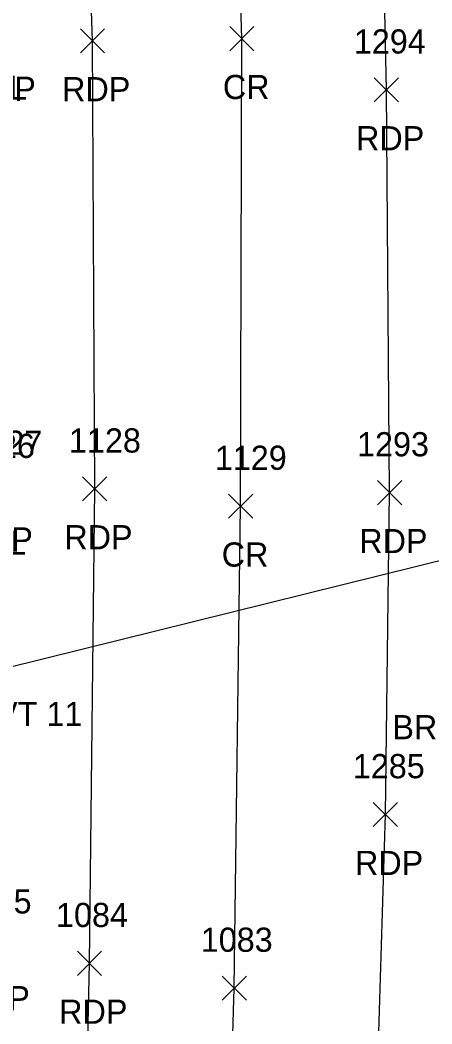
# Model space of a CAD drawing. Extents: x 1618262 to 1622220, y 273782 to 283685.
# Drawn here: x 1622046.2 to 1622080.2, y 282665.6 to 282748.6 of the extents above; entities that cross this region are included whole.
import ezdxf

# ---------------------------------------------------------------- set-up
doc = ezdxf.new("R2010")
doc.units = 0
for name, color, linetype in [('DCP', 7, 'Continuous'), ('P_A', 7, 'Continuous'), ('P_I', 7, 'Continuous'), ('P_TIC', 7, 'Continuous'), ('PET', 7, 'Continuous'), ('PRC', 7, 'Continuous'), ('R_A', 7, 'Continuous'), ('R_I', 7, 'Continuous'), ('S_C', 7, 'Continuous')]:
    doc.layers.add(name, color=color, linetype=linetype)

msp = doc.modelspace()

# ---------------------------------------------------------------- linework, layer by layer
at = {"layer": 'DCP'}
msp.add_lwpolyline([(1622023.295, 282689.629), (1622106.908, 282710.335)], dxfattribs=at)
at = {"layer": 'P_TIC'}
for points in [[(1622051.148, 282745.848), (1622053.148, 282747.848)], [(1622053.148, 282745.848), (1622051.148, 282747.848)], [(1622063.503, 282746.028), (1622065.503, 282748.028)], [(1622065.503, 282746.028), (1622063.503, 282748.028)], [(1622075.466, 282741.794), (1622077.466, 282743.794)], [(1622077.466, 282741.794), (1622075.466, 282743.794)], [(1622051.331, 282708.809), (1622053.331, 282710.809)], [(1622053.331, 282708.809), (1622051.331, 282710.809)], [(1622075.73, 282708.495), (1622077.73, 282710.495)], [(1622077.73, 282708.495), (1622075.73, 282710.495)], [(1622063.406, 282707.38), (1622065.406, 282709.38)], [(1622065.406, 282707.38), (1622063.406, 282709.38)], [(1622075.38, 282681.885), (1622077.38, 282683.885)], [(1622077.38, 282681.885), (1622075.38, 282683.885)], [(1622050.904, 282669.586), (1622052.904, 282671.586)], [(1622052.904, 282669.586), (1622050.904, 282671.586)], [(1622062.878, 282667.538), (1622064.878, 282669.538)], [(1622064.878, 282667.538), (1622062.878, 282669.538)]]:
    msp.add_lwpolyline(points, dxfattribs=at)
at = {"layer": 'PET'}
for points in [[(1622055.389, 282357.789), (1622060.735, 282405.546), (1622064, 282439.097), (1622067.385, 282476.749), (1622069.453, 282501.975), (1622071.171, 282531.215), (1622072.586, 282558.991), (1622074.383, 282609.306), (1622075.404, 282650.493), (1622076.38, 282682.885), (1622076.73, 282709.495), (1622076.466, 282742.794), (1622075.649, 282781.747), (1622073.854, 282831.38), (1622072.41, 282861.117), (1622070.969, 282880.709), (1622069.108, 282909.864), (1622067.074, 282934.336)], [(1622031.404, 282363.078), (1622036.529, 282409.612), (1622039.656, 282443.455), (1622042.912, 282478.81), (1622045.922, 282518.248), (1622048.156, 282558.34), (1622049.907, 282599.505), (1622051.114, 282634.143), (1622051.904, 282670.586), (1622052.331, 282709.809), (1622052.148, 282746.848), (1622051.427, 282768.15), (1622050.471, 282807.305), (1622048.588, 282847.854), (1622046.49, 282883.042), (1622043.219, 282932.276)]]:
    msp.add_lwpolyline(points, dxfattribs=at)
at = {"layer": 'PRC'}
msp.add_lwpolyline([(1622043.286, 282360.387), (1622048.896, 282407.643), (1622051.69, 282440.973), (1622055.31, 282477.626), (1622057.865, 282516.742), (1622059.99, 282557.513), (1622061.585, 282597.203), (1622062.841, 282633.199), (1622063.878, 282668.538), (1622064.406, 282708.38), (1622064.503, 282747.028), (1622063.87, 282768.185), (1622062.59, 282807.537), (1622060.956, 282848.034), (1622058.907, 282883.676), (1622055.26, 282933.108)], dxfattribs=at)

# ---------------------------------------------------------------- texts
at = {"layer": 'P_A'}
for s, p in [('SHP', (1622041.963, 282741.882)), ('RDP', (1622049.637, 282741.848)), ('CR', (1622062.936, 282742.028)), ('RDP', (1622073.954, 282737.794)), ('SHP', (1622041.715, 282704.624)), ('RDP', (1622049.819, 282704.809)), ('RDP', (1622074.219, 282704.495)), ('CR', (1622062.839, 282703.38)), ('RDP', (1622073.868, 282677.885)), ('SHP', (1622041.467, 282666.705)), ('RDP', (1622049.392, 282665.586))]:
    msp.add_text(s, height=2, dxfattribs=at).set_placement(p)
at = {"layer": 'P_I'}
for s, p in [('1294', (1622073.773, 282745.794)), ('1127', (1622042.054, 282712.624)), ('1128', (1622050.205, 282712.809)), ('1293', (1622074.038, 282712.495)), ('1129', (1622062.272, 282711.38)), ('1285', (1622073.688, 282685.885)), ('1085', (1622041.16, 282674.705)), ('1084', (1622049.133, 282673.586)), ('1083', (1622061.107, 282671.538))]:
    msp.add_text(s, height=2, dxfattribs=at).set_placement(p)
at = {"layer": 'R_A'}
for p in [(1622041.224, 282741.97), (1622041.159, 282704.363)]:
    msp.add_text('GRL', height=2, dxfattribs=at).set_placement(p)
at = {"layer": 'R_I'}
msp.add_text('1126', height=2, dxfattribs=at).set_placement((1622041.434, 282712.363))
at = {"layer": 'S_C'}
for p in [(1622029.462, 282690.198), (1622076.96, 282689.108)]:
    msp.add_text('BRIDGE 51 VT 11', height=2, dxfattribs=at).set_placement(p)

doc.saveas('drawing.dxf')
